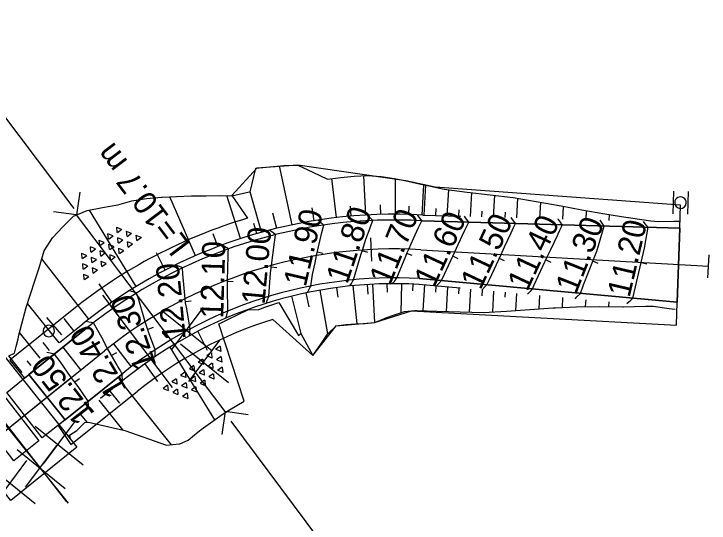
# Model space of a CAD drawing. Extents: x 554247.5 to 554326.1, y 6593477.6 to 6593537.1.
# Drawn here: x 554296.08 to 554326.13, y 6593515.09 to 6593537.09 of the extents above; entities that cross this region are included whole.
import ezdxf

# ---------------------------------------------------------------- set-up
doc = ezdxf.new("R2010")
doc.units = 0
for name, color, linetype in [('ASF', 7, 'Continuous'), ('BETOON', 7, 'Continuous'), ('FILL ASF KT', 7, 'Continuous'), ('FILL ROHELINE', 7, 'Continuous'), ('HATCH SILLUTIS', 7, 'Continuous'), ('KRAAV PUHASTAMINE', 7, 'Continuous'), ('LIIKLUSMÄRK', 7, 'Continuous'), ('LIKV', 7, 'Continuous'), ('NÕLV', 7, 'Continuous'), ('PIIRE TÕKKEPUU', 7, 'Continuous'), ('PK', 7, 'Continuous'), ('TELG', 7, 'Continuous'), ('TRUUP', 7, 'Continuous'), ('TRUUP TXT', 7, 'Continuous'), ('VERT', 7, 'Continuous')]:
    doc.layers.add(name, color=color, linetype=linetype)

msp = doc.modelspace()

# ---------------------------------------------------------------- linework, layer by layer
at = {"layer": 'ASF'}
for points in [[(554313.738, 6593528.147), (554324.87, 6593527.83), (554324.75, 6593524.63), (554313.595, 6593525.652)], [(554296.722, 6593521.505), (554299.215, 6593523.504)], [(554300.78, 6593521.555), (554298.289, 6593519.555), (554296.722, 6593521.505)]]:
    msp.add_lwpolyline(points, dxfattribs=at)
for radius in [21.25, 18.75]:
    msp.add_arc((554312.517, 6593506.933), radius, 86.7045, 128.7536, dxfattribs=at)
at = {"layer": 'BETOON'}
for points in [[(554292.815, 6593519.97), (554295.679, 6593522.269), (554298.802, 6593518.364), (554295.944, 6593516.07)], [(554296.724, 6593521.505), (554298.289, 6593519.555), (554297.304, 6593518.765), (554295.767, 6593520.736)], [(554295.622, 6593520.62), (554297.159, 6593518.648), (554296.078, 6593517.781), (554294.541, 6593519.752)]]:
    msp.add_lwpolyline(points, close=True, dxfattribs=at)
msp.add_lwpolyline([(554295.081, 6593520.186), (554298.344, 6593516.002)], dxfattribs=at)
at = {"layer": 'FILL ASF KT'}
msp.add_line((554299.215, 6593523.504), (554296.722, 6593521.505), dxfattribs=at)
for points in [[(554313.595, 6593525.652), (554324.75, 6593524.63), (554324.87, 6593527.83), (554313.738, 6593528.147)], [(554296.722, 6593521.505), (554298.289, 6593519.555), (554300.78, 6593521.555)]]:
    msp.add_lwpolyline(points, dxfattribs=at)
for radius in [21.25, 18.75]:
    msp.add_arc((554312.517, 6593506.933), radius, 86.7045, 128.7536, dxfattribs=at)
at = {"layer": 'FILL ROHELINE'}
for p, q in [((554296.529, 6593521.349), (554299.215, 6593523.504)), ((554298.543, 6593518.477), (554301.406, 6593520.775))]:
    msp.add_line(p, q, dxfattribs=at)
for points in [[(554313.738, 6593528.147), (554324.868, 6593527.83), (554324.897, 6593528.83), (554314.281, 6593529.597), (554313.015, 6593529.882), (554308.35, 6593530.55), (554306.584, 6593530.424), (554305.504, 6593529.244), (554306.171, 6593528.258)], [(554313.738, 6593528.147), (554324.868, 6593527.83), (554324.897, 6593528.83), (554314.281, 6593529.597), (554313.015, 6593529.882), (554308.35, 6593530.55), (554306.584, 6593530.424), (554305.504, 6593529.244), (554306.171, 6593528.258)], [(554307.265, 6593523.888), (554308.998, 6593522.335), (554310.003, 6593523.61), (554311.662, 6593523.748), (554313.264, 6593524.265), (554324.714, 6593523.634), (554324.75, 6593524.63), (554313.595, 6593525.652)], [(554307.265, 6593523.888), (554308.998, 6593522.335), (554310.003, 6593523.61), (554311.662, 6593523.748), (554313.264, 6593524.265), (554324.714, 6593523.634), (554324.75, 6593524.63), (554313.595, 6593525.652)], [(554298.589, 6593524.284), (554295.903, 6593522.128), (554296.529, 6593521.349)], [(554298.589, 6593524.284), (554295.903, 6593522.128), (554296.529, 6593521.349)], [(554296.529, 6593521.349), (554299.215, 6593523.504)], [(554300.78, 6593521.555), (554297.983, 6593519.31), (554298.543, 6593518.477)], [(554300.78, 6593521.555), (554297.983, 6593519.31), (554298.543, 6593518.477)], [(554298.543, 6593518.477), (554301.406, 6593520.775)]]:
    msp.add_lwpolyline(points, dxfattribs=at)
for radius, start in [(22.25, 106.5713), (22.25, 106.5713), (21.25, 86.7045), (21.25, 86.7045), (18.75, 86.7045), (18.75, 86.7045), (17.75, 107.2096), (17.75, 107.2096)]:
    msp.add_arc((554312.517, 6593506.933), radius, start, 128.7536, dxfattribs=at)
at = {"layer": 'HATCH SILLUTIS'}
for p, q in [((554300.732, 6593527.777), (554300.521, 6593527.863)), ((554300.544, 6593527.645), (554300.522, 6593527.872)), ((554300.551, 6593527.64), (554300.741, 6593527.781)), ((554300.966, 6593527.472), (554300.944, 6593527.699)), ((554301.155, 6593527.604), (554300.944, 6593527.69)), ((554299.787, 6593527.082), (554299.765, 6593527.31)), ((554300.354, 6593527.495), (554300.142, 6593527.582)), ((554300.165, 6593527.364), (554300.143, 6593527.591)), ((554300.173, 6593527.359), (554300.362, 6593527.5)), ((554300.776, 6593527.322), (554300.565, 6593527.409)), ((554300.588, 6593527.191), (554300.566, 6593527.418)), ((554300.595, 6593527.186), (554300.785, 6593527.326)), ((554300.974, 6593527.467), (554301.163, 6593527.608)), ((554301.577, 6593527.43), (554301.366, 6593527.517)), ((554301.389, 6593527.299), (554301.367, 6593527.526)), ((554301.396, 6593527.294), (554301.586, 6593527.435)), ((554299.597, 6593526.933), (554299.385, 6593527.019)), ((554299.408, 6593526.801), (554299.386, 6593527.028)), ((554299.975, 6593527.214), (554299.764, 6593527.301)), ((554299.794, 6593527.078), (554299.983, 6593527.218)), ((554300.398, 6593527.041), (554300.186, 6593527.127)), ((554300.209, 6593526.909), (554300.187, 6593527.136)), ((554300.217, 6593526.904), (554300.406, 6593527.045)), ((554301.01, 6593527.017), (554300.988, 6593527.245)), ((554301.199, 6593527.149), (554300.988, 6593527.236)), ((554301.018, 6593527.013), (554301.207, 6593527.153)), ((554299.218, 6593526.651), (554299.007, 6593526.738)), ((554299.03, 6593526.52), (554299.008, 6593526.747)), ((554299.416, 6593526.796), (554299.605, 6593526.937)), ((554300.019, 6593526.759), (554299.808, 6593526.846)), ((554299.831, 6593526.628), (554299.809, 6593526.855)), ((554299.838, 6593526.623), (554300.027, 6593526.764)), ((554300.82, 6593526.868), (554300.609, 6593526.954)), ((554300.632, 6593526.736), (554300.61, 6593526.963)), ((554300.639, 6593526.731), (554300.828, 6593526.872)), ((554299.037, 6593526.515), (554299.226, 6593526.655)), ((554299.641, 6593526.478), (554299.429, 6593526.565)), ((554299.452, 6593526.346), (554299.43, 6593526.574)), ((554299.46, 6593526.342), (554299.649, 6593526.482)), ((554300.442, 6593526.586), (554300.23, 6593526.673)), ((554300.253, 6593526.455), (554300.231, 6593526.682)), ((554300.261, 6593526.45), (554300.45, 6593526.59)), ((554299.262, 6593526.197), (554299.051, 6593526.283)), ((554299.074, 6593526.065), (554299.052, 6593526.292)), ((554299.081, 6593526.06), (554299.27, 6593526.201)), ((554299.685, 6593526.023), (554299.473, 6593526.11)), ((554299.496, 6593525.892), (554299.474, 6593526.119)), ((554300.063, 6593526.305), (554299.852, 6593526.391)), ((554299.875, 6593526.173), (554299.853, 6593526.4)), ((554299.882, 6593526.168), (554300.071, 6593526.309)), ((554299.306, 6593525.742), (554299.095, 6593525.829)), ((554299.118, 6593525.61), (554299.096, 6593525.838)), ((554299.504, 6593525.887), (554299.693, 6593526.028)), ((554299.125, 6593525.606), (554299.314, 6593525.746)), ((554304.987, 6593522.734), (554304.797, 6593522.594)), ((554304.805, 6593522.598), (554305.017, 6593522.511)), ((554304.994, 6593522.729), (554305.016, 6593522.502)), ((554304.608, 6593522.453), (554304.419, 6593522.312)), ((554304.427, 6593522.316), (554304.638, 6593522.23)), ((554304.616, 6593522.448), (554304.638, 6593522.221)), ((554305.031, 6593522.28), (554304.841, 6593522.139)), ((554305.038, 6593522.275), (554305.06, 6593522.048)), ((554304.229, 6593522.171), (554304.04, 6593522.031)), ((554304.048, 6593522.035), (554304.26, 6593521.948)), ((554304.237, 6593522.167), (554304.259, 6593521.939)), ((554304.652, 6593521.998), (554304.463, 6593521.858)), ((554304.66, 6593521.993), (554304.682, 6593521.766)), ((554304.849, 6593522.143), (554305.061, 6593522.057)), ((554303.472, 6593521.609), (554303.283, 6593521.468)), ((554303.48, 6593521.604), (554303.502, 6593521.377)), ((554303.851, 6593521.89), (554303.662, 6593521.749)), ((554303.67, 6593521.754), (554303.881, 6593521.667)), ((554303.859, 6593521.885), (554303.881, 6593521.658)), ((554304.273, 6593521.717), (554304.084, 6593521.576)), ((554304.281, 6593521.712), (554304.303, 6593521.485)), ((554304.471, 6593521.862), (554304.682, 6593521.775)), ((554305.075, 6593521.825), (554304.885, 6593521.684)), ((554304.893, 6593521.689), (554305.105, 6593521.602)), ((554305.082, 6593521.82), (554305.104, 6593521.593)), ((554303.094, 6593521.327), (554302.905, 6593521.186)), ((554303.101, 6593521.322), (554303.123, 6593521.095)), ((554303.291, 6593521.472), (554303.503, 6593521.386)), ((554303.895, 6593521.435), (554303.706, 6593521.295)), ((554303.714, 6593521.299), (554303.925, 6593521.212)), ((554303.903, 6593521.431), (554303.925, 6593521.203)), ((554304.092, 6593521.58), (554304.304, 6593521.494)), ((554304.696, 6593521.544), (554304.507, 6593521.403)), ((554304.515, 6593521.407), (554304.726, 6593521.321)), ((554304.704, 6593521.539), (554304.726, 6593521.312)), ((554302.715, 6593521.046), (554302.526, 6593520.905)), ((554302.723, 6593521.041), (554302.745, 6593520.814)), ((554302.913, 6593521.191), (554303.124, 6593521.104)), ((554303.516, 6593521.154), (554303.327, 6593521.013)), ((554303.335, 6593521.018), (554303.547, 6593520.931)), ((554303.524, 6593521.149), (554303.546, 6593520.922)), ((554304.317, 6593521.262), (554304.128, 6593521.121)), ((554304.136, 6593521.126), (554304.348, 6593521.039)), ((554304.325, 6593521.257), (554304.347, 6593521.03)), ((554302.534, 6593520.909), (554302.746, 6593520.823)), ((554303.138, 6593520.873), (554302.949, 6593520.732)), ((554302.957, 6593520.736), (554303.168, 6593520.65)), ((554303.145, 6593520.868), (554303.167, 6593520.641)), ((554303.56, 6593520.699), (554303.371, 6593520.559)), ((554303.939, 6593520.981), (554303.75, 6593520.84)), ((554303.758, 6593520.844), (554303.969, 6593520.758)), ((554303.946, 6593520.976), (554303.968, 6593520.749)), ((554303.379, 6593520.563), (554303.591, 6593520.476)), ((554303.568, 6593520.695), (554303.59, 6593520.467))]:
    msp.add_line(p, q, dxfattribs=at)
at = {"layer": 'KRAAV PUHASTAMINE'}
for points in [[(554298.682, 6593528.687), (554292.32, 6593537.088)], [(554313.558, 6593508.65), (554305.471, 6593519.49)]]:
    msp.add_lwpolyline(points, dxfattribs=at)
at = {"layer": 'LIIKLUSMÄRK'}
for points in [[(554324.594, 6593529.436), (554324.564, 6593528.452)], [(554325.219, 6593529.417), (554325.189, 6593528.433)], [(554298.144, 6593523.218), (554297.503, 6593523.966)]]:
    msp.add_lwpolyline(points, dxfattribs=at)
for centre, start, end in [((554324.892, 6593528.933), 358.2702, 178.2702), ((554324.892, 6593528.933), 358.2702, 178.2702), ((554324.892, 6593528.933), 178.2702, 358.2702), ((554324.892, 6593528.933), 178.2702, 358.2702), ((554297.585, 6593523.39), 40.559, 220.559), ((554297.585, 6593523.39), 40.559, 220.559), ((554297.585, 6593523.39), 220.559, 40.559), ((554297.585, 6593523.39), 220.559, 40.559)]:
    msp.add_arc(centre, 0.25, start, end, dxfattribs=at)
at = {"layer": 'LIKV'}
for points in [[(554302.91, 6593522.595), (554304.267, 6593524.404)], [(554302.548, 6593524.223), (554304.629, 6593522.55)], [(554303.273, 6593522.83), (554305.355, 6593521.156)], [(554303.635, 6593521.202), (554304.993, 6593523.011)], [(554296.995, 6593519.279), (554299.077, 6593517.606)], [(554297.358, 6593517.651), (554298.715, 6593519.46)], [(554296.575, 6593516.634), (554297.933, 6593518.443)], [(554296.213, 6593518.262), (554298.295, 6593516.589)], [(554295.281, 6593515.979), (554296.639, 6593517.788)], [(554294.919, 6593517.607), (554297.001, 6593515.933)]]:
    msp.add_lwpolyline(points, dxfattribs=at)
at = {"layer": 'NÕLV'}
for p, q in [((554308.1, 6593527.972), (554307.565, 6593530.518)), ((554311.296, 6593528.396), (554311.199, 6593530.096)), ((554310.024, 6593528.286), (554309.827, 6593529.976)), ((554312.571, 6593528.432), (554312.575, 6593529.967)), ((554313.722, 6593528.399), (554313.795, 6593529.707)), ((554313.812, 6593528.394), (554313.887, 6593529.683)), ((554314.812, 6593528.367), (554314.877, 6593529.487)), ((554303.93, 6593526.641), (554302.819, 6593529.19)), ((554305.878, 6593527.381), (554305.275, 6593529.238)), ((554306.777, 6593527.652), (554306.292, 6593529.402)), ((554315.812, 6593528.338), (554315.871, 6593529.37)), ((554316.811, 6593528.31), (554316.865, 6593529.252)), ((554317.811, 6593528.281), (554317.859, 6593529.121)), ((554311.933, 6593528.424), (554311.922, 6593528.836)), ((554318.81, 6593528.253), (554318.85, 6593528.947)), ((554301.356, 6593525.308), (554299.348, 6593528.614)), ((554309.059, 6593528.151), (554308.967, 6593528.711)), ((554310.659, 6593528.35), (554310.622, 6593528.775)), ((554313.147, 6593528.422), (554313.157, 6593528.778)), ((554314.312, 6593528.38), (554314.329, 6593528.679)), ((554315.312, 6593528.353), (554315.327, 6593528.621)), ((554316.311, 6593528.324), (554316.326, 6593528.571)), ((554317.311, 6593528.296), (554317.324, 6593528.52)), ((554319.81, 6593528.224), (554319.842, 6593528.772)), ((554320.81, 6593528.196), (554320.832, 6593528.586)), ((554307.436, 6593527.822), (554307.276, 6593528.478)), ((554321.809, 6593528.167), (554321.824, 6593528.416)), ((554306.578, 6593527.595), (554306.452, 6593528.035)), ((554304.895, 6593527.034), (554304.687, 6593527.583)), ((554302.62, 6593526.018), (554302.236, 6593526.759)), ((554299.316, 6593523.901), (554297.286, 6593526.51)), ((554300.315, 6593524.634), (554299.767, 6593525.429)), ((554310.019, 6593525.262), (554310.074, 6593524.856)), ((554310.735, 6593525.346), (554310.894, 6593523.697)), ((554311.354, 6593525.395), (554311.38, 6593524.978)), ((554311.578, 6593525.409), (554311.662, 6593523.748)), ((554312.201, 6593525.429), (554312.207, 6593525.066)), ((554312.825, 6593525.429), (554312.804, 6593524.181)), ((554313.325, 6593525.417), (554313.312, 6593525.13)), ((554313.823, 6593525.38), (554313.759, 6593524.269)), ((554314.321, 6593525.334), (554314.305, 6593525.064)), ((554314.819, 6593525.289), (554314.758, 6593524.237)), ((554315.317, 6593525.243), (554315.302, 6593524.987)), ((554308.693, 6593525.032), (554308.82, 6593524.428)), ((554309.307, 6593525.152), (554309.64, 6593523.259)), ((554315.815, 6593525.197), (554315.758, 6593524.205)), ((554316.313, 6593525.152), (554316.299, 6593524.911)), ((554316.811, 6593525.106), (554316.759, 6593524.209)), ((554317.308, 6593525.061), (554317.297, 6593524.856)), ((554317.806, 6593525.015), (554317.764, 6593524.275)), ((554318.802, 6593524.924), (554318.769, 6593524.343)), ((554308.082, 6593524.893), (554308.482, 6593523.273)), ((554319.798, 6593524.833), (554319.773, 6593524.403)), ((554320.794, 6593524.741), (554320.777, 6593524.44)), ((554321.79, 6593524.65), (554321.778, 6593524.441)), ((554298.035, 6593522.878), (554296.668, 6593524.582)), ((554298.674, 6593523.391), (554298.248, 6593523.923)), ((554297.209, 6593522.215), (554296.324, 6593523.317)), ((554304.021, 6593523.366), (554304.436, 6593522.563)), ((554297.622, 6593522.546), (554297.34, 6593522.898)), ((554302.819, 6593522.686), (554304.749, 6593519.55)), ((554296.429, 6593521.589), (554295.851, 6593522.308)), ((554296.819, 6593521.902), (554296.657, 6593522.104)), ((554301.737, 6593521.967), (554302.282, 6593521.206)), ((554300.707, 6593521.175), (554302.876, 6593518.473)), ((554300.224, 6593520.788), (554300.636, 6593520.275)), ((554299.742, 6593520.401), (554300.774, 6593519.115)), ((554299.352, 6593520.088), (554299.511, 6593519.89)), ((554298.962, 6593519.775), (554299.226, 6593519.447)), ((554298.182, 6593519.149), (554298.54, 6593518.703))]:
    msp.add_line(p, q, dxfattribs=at)
for points in [[(554306.292, 6593529.402), (554306.529, 6593530.418), (554307.136, 6593530.484), (554307.742, 6593530.532), (554308.35, 6593530.55), (554309.002, 6593530.249), (554309.633, 6593529.953), (554310.209, 6593530.022), (554310.787, 6593530.072), (554311.366, 6593530.105), (554311.947, 6593530.069), (554312.526, 6593529.976), (554313.099, 6593529.866), (554313.667, 6593529.738), (554313.828, 6593529.699), (554313.887, 6593529.683)], [(554313.887, 6593529.683), (554314.676, 6593529.51), (554315.67, 6593529.393), (554316.665, 6593529.277), (554317.66, 6593529.155), (554318.652, 6593528.982), (554319.643, 6593528.808), (554319.741, 6593528.791), (554320.634, 6593528.62), (554321.626, 6593528.448), (554322.619, 6593528.29), (554322.647, 6593528.285), (554323.115, 6593528.215), (554323.612, 6593528.151), (554323.926, 6593528.116), (554324.612, 6593528.127), (554324.888, 6593528.138)], [(554295.851, 6593522.308), (554296.109, 6593522.43), (554296.172, 6593522.718), (554296.254, 6593523.049), (554296.295, 6593523.205), (554296.612, 6593524.407), (554296.977, 6593525.549), (554297.153, 6593526.073), (554297.169, 6593526.122), (554297.388, 6593526.85), (554297.747, 6593527.42), (554298.192, 6593527.889), (554298.651, 6593528.346), (554299.247, 6593528.595), (554299.91, 6593528.717), (554300.564, 6593528.832), (554301.176, 6593529.006), (554301.812, 6593529.115), (554302.463, 6593529.17), (554302.48, 6593529.171), (554303.11, 6593529.206), (554303.751, 6593529.228), (554304.386, 6593529.234), (554305.007, 6593529.249), (554305.387, 6593529.234), (554305.621, 6593529.255), (554306.192, 6593529.38), (554306.292, 6593529.402)], [(554298.54, 6593518.703), (554298.476, 6593518.89), (554298.792, 6593519.088), (554298.96, 6593519.244), (554299.15, 6593519.441), (554299.306, 6593519.453), (554300.879, 6593519.09), (554302.677, 6593518.448), (554303.22, 6593518.514), (554303.25, 6593518.519), (554303.604, 6593518.666), (554303.888, 6593518.902), (554304.178, 6593519.131), (554304.474, 6593519.354), (554304.776, 6593519.569), (554305.083, 6593519.778), (554305.396, 6593519.979), (554305.714, 6593520.173), (554306.037, 6593520.36), (554304.94, 6593523.691), (554304.951, 6593523.697), (554305.349, 6593523.903), (554305.765, 6593524.105), (554306.186, 6593524.296), (554306.666, 6593524.319), (554306.928, 6593524.413), (554307.098, 6593524.472), (554307.532, 6593524.626), (554308.373, 6593523.187), (554308.482, 6593523.273)], [(554311.662, 6593523.748), (554311.681, 6593523.756), (554312.098, 6593523.928), (554312.159, 6593523.951), (554312.523, 6593524.087), (554312.956, 6593524.233), (554313.391, 6593524.278), (554313.516, 6593524.277), (554314.373, 6593524.249), (554315.372, 6593524.217), (554316.372, 6593524.185), (554317.378, 6593524.249), (554318.383, 6593524.318), (554319.389, 6593524.383), (554319.488, 6593524.389), (554320.393, 6593524.434), (554321.396, 6593524.448), (554322.396, 6593524.429), (554322.425, 6593524.43), (554322.898, 6593524.449), (554323.4, 6593524.462), (554323.716, 6593524.465), (554324.396, 6593524.366), (554324.665, 6593524.325)], [(554308.482, 6593523.273), (554308.998, 6593522.335), (554309.313, 6593522.769), (554309.637, 6593523.256), (554310.003, 6593523.61), (554310.421, 6593523.662), (554310.841, 6593523.695), (554311.262, 6593523.712), (554311.662, 6593523.748)]]:
    msp.add_lwpolyline(points, dxfattribs=at)
at = {"layer": 'PIIRE TÕKKEPUU'}
for points in [[(554313.749, 6593528.397), (554315.396, 6593528.35)], [(554315.368, 6593525.238), (554313.576, 6593525.402)], [(554298.05, 6593522.89), (554299.058, 6593523.699)], [(554300.377, 6593522.827), (554301.146, 6593521.841)], [(554298.97, 6593521.705), (554298.201, 6593522.69)], [(554300.936, 6593521.36), (554299.827, 6593520.469)]]:
    msp.add_lwpolyline(points, dxfattribs=at)
for radius, start in [(21.5, 86.7142), (18.5, 86.7176)]:
    msp.add_arc((554312.517, 6593506.933), radius, start, 128.7536, dxfattribs=at)
at = {"layer": 'PK'}
for p, q in [((554311.55, 6593526.409), (554311.5, 6593527.407)), ((554326.072, 6593525.684), (554326.129, 6593526.683))]:
    msp.add_line(p, q, dxfattribs=at)
at = {"layer": 'TELG'}
for points in [[(554313.667, 6593526.899), (554326.101, 6593526.183)], [(554291.196, 6593515.464), (554299.997, 6593522.529)], [(554293.707, 6593517.48), (554298.559, 6593521.375)], [(554293.97, 6593521.484), (554298.416, 6593515.947)]]:
    msp.add_lwpolyline(points, dxfattribs=at)
msp.add_arc((554312.517, 6593506.933), 20, 86.7045, 128.7536, dxfattribs=at)
at = {"layer": 'TRUUP'}
for p, q in [((554299.904, 6593524.931), (554301.013, 6593523.464)), ((554301.013, 6593523.464), (554302.92, 6593520.943))]:
    msp.add_line(p, q, dxfattribs=at)
for points in [[(554298.922, 6593529.393), (554298.785, 6593528.402), (554297.794, 6593528.54)], [(554305.21, 6593519.903), (554298.785, 6593528.402)], [(554306.2, 6593519.766), (554305.21, 6593519.903), (554305.072, 6593518.913)]]:
    msp.add_lwpolyline(points, dxfattribs=at)
at = {"layer": 'VERT'}
for p, q in [((554309.438, 6593526.735), (554309.195, 6593526.792)), ((554311.373, 6593526.776), (554311.136, 6593526.857)), ((554313.294, 6593526.644), (554313.063, 6593526.738)), ((554315.275, 6593526.51), (554315.049, 6593526.617)), ((554317.281, 6593526.416), (554317.055, 6593526.522)), ((554319.303, 6593526.354), (554319.077, 6593526.46)), ((554307.45, 6593526.119), (554307.201, 6593526.142)), ((554321.336, 6593526.307), (554321.104, 6593526.399)), ((554323.434, 6593526.279), (554323.19, 6593526.336)), ((554305.559, 6593525.517), (554305.309, 6593525.525)), ((554303.745, 6593524.67), (554303.496, 6593524.647)), ((554302.096, 6593523.541), (554301.86, 6593523.459)), ((554300.511, 6593522.45), (554300.296, 6593522.324)), ((554298.91, 6593521.328), (554298.712, 6593521.176))]:
    msp.add_line(p, q, dxfattribs=at)
for points in [[(554310.604, 6593525.333), (554310.667, 6593525.44), (554310.735, 6593525.554), (554310.764, 6593525.599), (554310.894, 6593526.087), (554311.048, 6593526.577), (554311.092, 6593526.727), (554311.146, 6593526.884), (554311.294, 6593527.351), (554311.473, 6593527.841), (554311.478, 6593527.856), (554311.591, 6593528.161), (554311.455, 6593528.306), (554311.365, 6593528.401)], [(554312.45, 6593525.432), (554312.473, 6593525.464), (554312.524, 6593525.532), (554312.603, 6593525.639), (554312.637, 6593525.681), (554313.017, 6593526.626), (554313.077, 6593526.774), (554313.145, 6593526.922), (554313.346, 6593527.389), (554313.572, 6593527.855), (554313.715, 6593528.149), (554313.595, 6593528.306), (554313.538, 6593528.379), (554313.514, 6593528.408)], [(554314.345, 6593525.332), (554314.441, 6593525.438), (554314.556, 6593525.564), (554314.687, 6593525.845), (554315.142, 6593526.815), (554315.288, 6593527.127), (554315.575, 6593527.741), (554315.682, 6593527.968), (554315.739, 6593528.09), (554315.606, 6593528.271), (554315.551, 6593528.346)], [(554316.311, 6593525.152), (554316.436, 6593525.289), (554316.522, 6593525.383), (554316.632, 6593525.618), (554317.138, 6593526.7), (554317.289, 6593527.022), (554317.572, 6593527.626), (554317.694, 6593527.886), (554317.763, 6593528.033), (554317.608, 6593528.243), (554317.575, 6593528.288)], [(554318.277, 6593524.972), (554318.431, 6593525.14), (554318.488, 6593525.203), (554318.57, 6593525.378), (554319.135, 6593526.585), (554319.29, 6593526.916), (554319.569, 6593527.511), (554319.601, 6593527.579), (554319.681, 6593527.751), (554319.745, 6593527.887), (554319.777, 6593527.975), (554319.701, 6593528.091), (554319.62, 6593528.201), (554319.609, 6593528.215), (554319.598, 6593528.23)], [(554308.776, 6593525.05), (554308.79, 6593525.082), (554308.829, 6593525.163), (554308.885, 6593525.283), (554308.91, 6593525.331), (554308.99, 6593525.83), (554309.094, 6593526.332), (554309.161, 6593526.648), (554309.394, 6593527.648), (554309.431, 6593527.805), (554309.476, 6593527.963), (554309.327, 6593528.094), (554309.227, 6593528.178)], [(554320.335, 6593524.783), (554320.418, 6593524.864), (554320.572, 6593525.013), (554320.703, 6593525.388), (554321.132, 6593526.47), (554321.276, 6593526.834), (554321.593, 6593527.923), (554321.592, 6593527.924), (554321.426, 6593528.178)], [(554322.578, 6593524.578), (554322.74, 6593524.722), (554322.834, 6593524.805), (554322.947, 6593525.292), (554323.194, 6593526.351), (554323.338, 6593526.97), (554323.49, 6593527.869), (554323.414, 6593527.965), (554323.287, 6593528.125)], [(554306.986, 6593524.586), (554307.006, 6593524.645), (554307.027, 6593524.704), (554307.091, 6593524.879), (554307.175, 6593525.894), (554307.198, 6593526.108), (554307.203, 6593526.166), (554307.209, 6593526.215), (554307.342, 6593527.233), (554307.351, 6593527.307), (554307.392, 6593527.554), (554307.346, 6593527.587), (554307.23, 6593527.67), (554307.158, 6593527.72), (554307.123, 6593527.744)], [(554305.251, 6593523.945), (554305.259, 6593523.98), (554305.28, 6593524.067), (554305.312, 6593524.196), (554305.326, 6593524.248), (554305.308, 6593525.266), (554305.306, 6593525.426), (554305.311, 6593525.588), (554305.341, 6593526.615), (554305.346, 6593526.776), (554305.358, 6593526.939), (554305.186, 6593527.038), (554305.105, 6593527.084), (554305.072, 6593527.101)], [(554303.666, 6593523.178), (554303.668, 6593523.192), (554303.702, 6593523.48), (554303.534, 6593524.415), (554303.5, 6593524.61), (554303.484, 6593524.775), (554303.383, 6593525.859), (554303.371, 6593526.113), (554303.331, 6593526.13), (554303.233, 6593526.169), (554303.057, 6593526.238)], [(554302.18, 6593522.274), (554302.184, 6593522.405), (554302.187, 6593522.579), (554301.91, 6593523.313), (554301.748, 6593523.785), (554301.472, 6593524.729), (554301.38, 6593525.03), (554301.172, 6593525.089), (554301.054, 6593525.12)], [(554300.771, 6593521.227), (554300.762, 6593521.512), (554300.761, 6593521.54), (554300.734, 6593521.582), (554300.669, 6593521.693), (554300.572, 6593521.851), (554300.537, 6593521.911), (554300.12, 6593522.625), (554299.872, 6593523.101), (554299.516, 6593523.739), (554299.31, 6593523.773), (554299.182, 6593523.796)], [(554299.304, 6593520.049), (554299.299, 6593520.192), (554299.294, 6593520.362), (554298.856, 6593520.989), (554298.559, 6593521.375), (554298.073, 6593522.076), (554297.83, 6593522.393), (554297.647, 6593522.427), (554297.507, 6593522.454)]]:
    msp.add_lwpolyline(points, dxfattribs=at)

# ---------------------------------------------------------------- texts
at = {"layer": 'TRUUP TXT'}
msp.add_text('L=10.7 m', height=1, rotation=127.0892, dxfattribs=at).set_placement((554303.74, 6593527.126))
at = {"layer": 'VERT'}
for s, rotation, p in [('11.90', 76.8716, (554308.69, 6593525.255)), ('11.80', 71.203, (554310.486, 6593525.375)), ('11.70', 67.8981, (554312.328, 6593525.297)), ('11.60', 64.9031, (554314.236, 6593525.217)), ('11.50', 64.9031, (554316.246, 6593525.121)), ('11.40', 64.9031, (554318.268, 6593525.059)), ('11.30', 68.3857, (554320.381, 6593524.951)), ('11.20', 76.8743, (554322.689, 6593524.797)), ('12.00', 84.8852, (554306.912, 6593524.503)), ('12.10', 88.3308, (554305.124, 6593523.917)), ('12.20', 95.3423, (554303.509, 6593523.029)), ('12.30', 108.9715, (554302.253, 6593521.89)), ('12.40', 120.2984, (554300.989, 6593520.863)), ('12.50', 127.5941, (554299.586, 6593519.814))]:
    msp.add_text(s, height=1, rotation=rotation, dxfattribs=at).set_placement(p)

doc.saveas('drawing.dxf')
